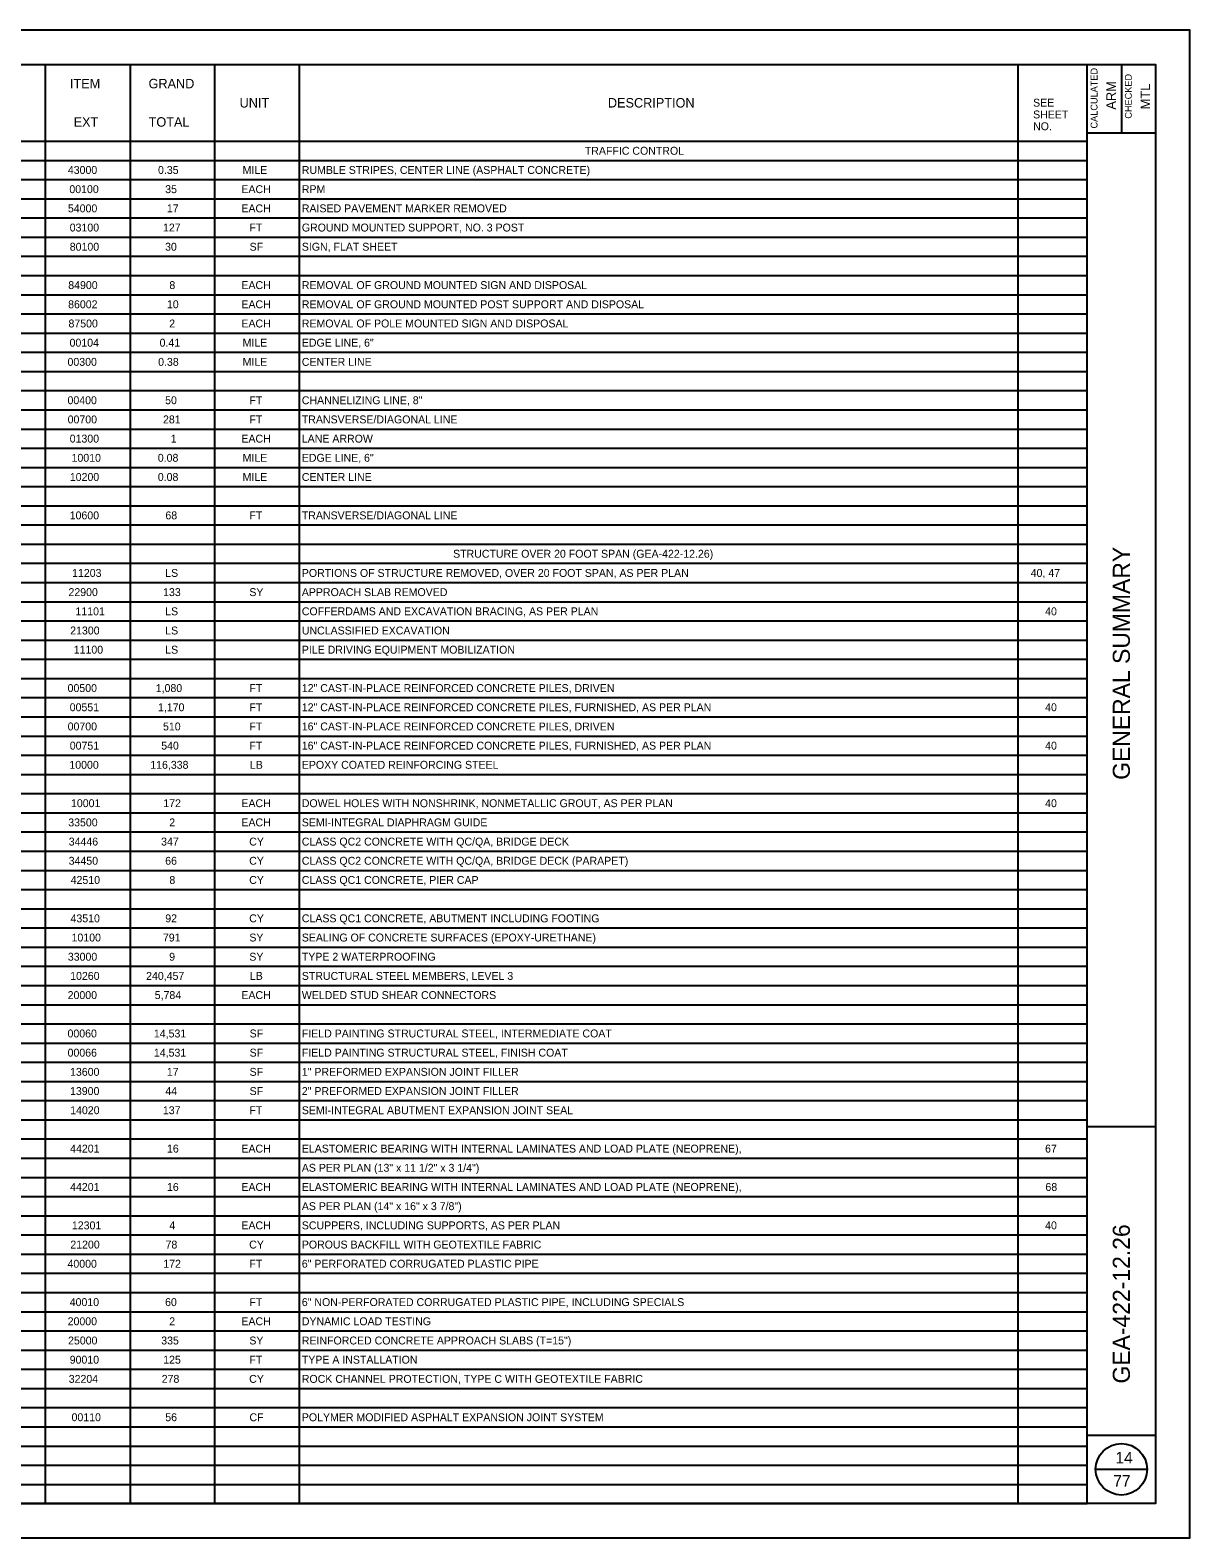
# Model space of a CAD drawing. Extents: x 0 to 34, y 0 to 22.
# Drawn here: x 17.07 to 34, y 0 to 22 of the extents above; entities that cross this region are included whole.
import ezdxf

# ---------------------------------------------------------------- set-up
doc = ezdxf.new("R2010")
doc.units = 0
for name, color, linetype in [('SH_Border', 7, 'Continuous'), ('SH_Cut_Line', 7, 'Continuous'), ('SH_Data', 7, 'Continuous'), ('SH_Text', 7, 'Continuous')]:
    doc.layers.add(name, color=color, linetype=linetype)

msp = doc.modelspace()

# ---------------------------------------------------------------- linework, layer by layer
at = {"layer": 'SH_Border'}
for p, q in [((32.5, 0.5), (32.5, 21.5)), ((33, 21.5), (33, 20.5)), ((32.5, 20.5), (33.5, 20.5)), ((32.5, 6), (33.5, 6)), ((32.5, 1.5), (33.5, 1.5))]:
    msp.add_line(p, q, dxfattribs=at)
msp.add_lwpolyline([(2, 21.5), (33.5, 21.5), (33.5, 0.5), (2, 0.5)], close=True, dxfattribs=at)
at = {"layer": 'SH_Cut_Line'}
msp.add_lwpolyline([(0, 0), (34, 0), (34, 22), (0, 22)], close=True, dxfattribs=at)
at = {"layer": 'SH_Data'}
msp.add_line((32.625, 1), (33.375, 1), dxfattribs=at)
msp.add_circle((33, 1), 0.375, dxfattribs=at)
at = {"layer": 'SH_Text'}
for p, q in [((2, 21.5), (32.5, 21.5)), ((17.299, 0.5), (17.299, 21.5)), ((18.535, 0.5), (18.535, 21.5)), ((19.77, 0.5), (19.77, 21.5)), ((21.005, 0.5), (21.005, 21.5)), ((31.495, 0.5), (31.495, 21.5)), ((32.5, 0.5), (32.5, 21.5)), ((14.055, 20.38), (32.5, 20.38)), ((19.77, 20.38), (32.5, 20.38)), ((2, 20.1), (32.5, 20.1)), ((2, 19.82), (32.5, 19.82)), ((2, 19.54), (32.5, 19.54)), ((2, 19.26), (32.5, 19.26)), ((2, 18.98), (32.5, 18.98)), ((2, 18.7), (32.5, 18.7)), ((2, 18.42), (32.5, 18.42)), ((2, 18.14), (32.5, 18.14)), ((2, 17.86), (32.5, 17.86)), ((2, 17.58), (32.5, 17.58)), ((2, 17.3), (32.5, 17.3)), ((2, 17.02), (32.5, 17.02)), ((2, 16.74), (32.5, 16.74)), ((2, 16.46), (32.5, 16.46)), ((2, 16.18), (32.5, 16.18)), ((2, 15.9), (32.5, 15.9)), ((2, 15.62), (32.5, 15.62)), ((2, 15.34), (32.5, 15.34)), ((2, 15.06), (32.5, 15.06)), ((2, 14.78), (32.5, 14.78)), ((2, 14.5), (32.5, 14.5)), ((2, 14.22), (32.5, 14.22)), ((2, 13.94), (32.5, 13.94)), ((2, 13.66), (32.5, 13.66)), ((2, 13.38), (32.5, 13.38)), ((2, 13.1), (32.5, 13.1)), ((2, 12.82), (32.5, 12.82)), ((2, 12.54), (32.5, 12.54)), ((2, 12.26), (32.5, 12.26)), ((2, 11.98), (32.5, 11.98)), ((2, 11.7), (32.5, 11.7)), ((2, 11.42), (32.5, 11.42)), ((2, 11.14), (32.5, 11.14)), ((2, 10.86), (32.5, 10.86)), ((2, 10.58), (32.5, 10.58)), ((2, 10.3), (32.5, 10.3)), ((2, 10.02), (32.5, 10.02)), ((2, 9.74), (32.5, 9.74)), ((2, 9.46), (32.5, 9.46)), ((2, 9.18), (32.5, 9.18)), ((2, 8.9), (32.5, 8.9)), ((2, 8.62), (32.5, 8.62)), ((2, 8.34), (32.5, 8.34)), ((2, 8.06), (32.5, 8.06)), ((2, 7.78), (32.5, 7.78)), ((2, 7.5), (32.5, 7.5)), ((2, 7.22), (32.5, 7.22)), ((2, 6.94), (32.5, 6.94)), ((2, 6.66), (32.5, 6.66)), ((2, 6.38), (32.5, 6.38)), ((2, 6.1), (32.5, 6.1)), ((2, 5.82), (32.5, 5.82)), ((2, 5.54), (32.5, 5.54)), ((2, 5.26), (32.5, 5.26)), ((2, 4.98), (32.5, 4.98)), ((2, 4.7), (32.5, 4.7)), ((2, 4.42), (32.5, 4.42)), ((2, 4.14), (32.5, 4.14)), ((2, 3.86), (32.5, 3.86)), ((2, 3.58), (32.5, 3.58)), ((2, 3.3), (32.5, 3.3)), ((2, 3.02), (32.5, 3.02)), ((2, 2.74), (32.5, 2.74)), ((2, 2.46), (32.5, 2.46)), ((2, 2.18), (32.5, 2.18)), ((2, 1.9), (32.5, 1.9)), ((2, 1.62), (32.5, 1.62)), ((2, 1.34), (32.5, 1.34)), ((2, 1.06), (32.5, 1.06)), ((2, 0.78), (32.5, 0.78)), ((2, 0.5), (32.5, 0.5))]:
    msp.add_line(p, q, dxfattribs=at)

# ---------------------------------------------------------------- texts
at = {"layer": 'SH_Data'}
for s, height, p in [('CALCULATED', 0.1, (32.652, 20.565)), ('CHECKED', 0.1, (33.152, 20.708)), ('ARM', 0.14, (32.92, 20.84)), ('MTL', 0.14, (33.42, 20.844)), ('GENERAL SUMMARY', 0.25, (33.125, 11.061)), ('GEA-422-12.26', 0.25, (33.125, 2.252))]:
    msp.add_text(s, height=height, rotation=90, dxfattribs=at).set_placement(p)
for s, p in [('14', (32.914, 1.085)), ('77', (32.882, 0.745))]:
    msp.add_text(s, height=0.17, dxfattribs=at).set_placement(p)
at = {"layer": 'SH_Text'}
for s, height, p in [('ITEM', 0.1384, (17.654, 21.151)), ('GRAND', 0.1384, (18.801, 21.151)), ('UNIT', 0.1384, (20.13, 20.871)), ('DESCRIPTION', 0.13841, (25.506, 20.871)), ('SEE', 0.1153, (31.712, 20.884)), ('EXT', 0.1384, (17.707, 20.591)), ('TOTAL', 0.1384, (18.802, 20.591)), ('SHEET', 0.1153, (31.712, 20.712)), ('NO.', 0.1153, (31.712, 20.54)), ('TRAFFIC CONTROL', 0.11534, (25.169, 20.182)), ('RUMBLE STRIPES, CENTER LINE (ASPHALT CONCRETE) ', 0.11534, (21.038, 19.902)), ('43000', 0.1153, (17.623, 19.902)), ('0.35', 0.1153, (18.939, 19.902)), ('MILE', 0.1153, (20.174, 19.902)), ('00100', 0.1153, (17.645, 19.622)), ('35', 0.1153, (19.044, 19.622)), ('EACH', 0.1153, (20.156, 19.622)), ('RPM ', 0.1153, (21.038, 19.622)), ('54000', 0.1153, (17.624, 19.342)), ('17', 0.1153, (19.068, 19.342)), ('EACH', 0.1153, (20.156, 19.342)), ('RAISED PAVEMENT MARKER REMOVED ', 0.11534, (21.038, 19.342)), ('03100', 0.1153, (17.65, 19.062)), ('127', 0.1153, (19.012, 19.062)), ('FT', 0.1153, (20.272, 19.062)), ('GROUND MOUNTED SUPPORT, NO. 3 POST ', 0.11534, (21.038, 19.062)), ('80100', 0.1153, (17.651, 18.782)), ('30', 0.1153, (19.042, 18.782)), ('SF', 0.1153, (20.276, 18.782)), ('SIGN, FLAT SHEET ', 0.11534, (21.038, 18.782)), ('84900', 0.1153, (17.629, 18.222)), ('8', 0.115, (19.105, 18.222)), ('EACH', 0.1153, (20.156, 18.222)), ('REMOVAL OF GROUND MOUNTED SIGN AND DISPOSAL ', 0.11534, (21.038, 18.222)), ('86002', 0.1153, (17.627, 17.942)), ('10', 0.1153, (19.069, 17.942)), ('EACH', 0.1153, (20.156, 17.942)), ('REMOVAL OF GROUND MOUNTED POST SUPPORT AND DISPOSAL ', 0.11534, (21.038, 17.942)), ('87500', 0.1153, (17.632, 17.662)), ('2', 0.115, (19.103, 17.662)), ('EACH', 0.1153, (20.156, 17.662)), ('REMOVAL OF POLE MOUNTED SIGN AND DISPOSAL ', 0.11534, (21.038, 17.662)), ('00104', 0.1153, (17.648, 17.382)), ('0.41', 0.1153, (18.962, 17.382)), ('MILE', 0.1153, (20.174, 17.382)), ('EDGE LINE, 6"', 0.11534, (21.038, 17.382)), ('00300', 0.1153, (17.618, 17.102)), ('0.38', 0.1153, (18.941, 17.102)), ('MILE', 0.1153, (20.174, 17.102)), ('CENTER LINE ', 0.11534, (21.038, 17.102)), ('00400', 0.1153, (17.618, 16.542)), ('50', 0.1153, (19.043, 16.542)), ('FT', 0.1153, (20.272, 16.542)), ('CHANNELIZING LINE, 8" ', 0.11534, (21.038, 16.542)), ('00700', 0.1153, (17.62, 16.262)), ('281', 0.1153, (19.012, 16.262)), ('FT', 0.1153, (20.272, 16.262)), ('TRANSVERSE/DIAGONAL LINE ', 0.11534, (21.038, 16.262)), ('01300', 0.1153, (17.65, 15.982)), ('1', 0.115, (19.125, 15.982)), ('EACH', 0.1153, (20.156, 15.982)), ('LANE ARROW ', 0.11534, (21.038, 15.982)), ('10010', 0.1153, (17.677, 15.702)), ('0.08', 0.1153, (18.936, 15.702)), ('MILE', 0.1153, (20.174, 15.702)), ('EDGE LINE, 6" ', 0.11534, (21.038, 15.702)), ('10200', 0.1153, (17.652, 15.422)), ('0.08', 0.1153, (18.936, 15.422)), ('MILE', 0.1153, (20.174, 15.422)), ('CENTER LINE ', 0.11534, (21.038, 15.422)), ('10600', 0.1153, (17.65, 14.862)), ('68', 0.1153, (19.047, 14.862)), ('FT', 0.1153, (20.272, 14.862)), ('TRANSVERSE/DIAGONAL LINE ', 0.11534, (21.038, 14.862)), ('STRUCTURE OVER 20 FOOT SPAN (GEA-422-12.26)', 0.11534, (23.246, 14.302)), ('11203', 0.1153, (17.685, 14.022)), ('LS', 0.1153, (19.044, 14.022)), ('PORTIONS OF STRUCTURE REMOVED, OVER 20 FOOT SPAN, AS PER PLAN', 0.11534, (21.038, 14.022)), ('40, 47', 0.1153, (31.677, 14.022)), ('22900', 0.1153, (17.632, 13.742)), ('133', 0.1153, (19.013, 13.742)), ('SY', 0.1153, (20.272, 13.742)), ('APPROACH SLAB REMOVED', 0.11534, (21.038, 13.742)), ('11101', 0.1153, (17.734, 13.462)), ('LS', 0.1153, (19.044, 13.462)), ('COFFERDAMS AND EXCAVATION BRACING, AS PER PLAN', 0.11534, (21.038, 13.462)), ('40', 0.1153, (31.888, 13.462)), ('21300', 0.1153, (17.657, 13.182)), ('LS', 0.1153, (19.044, 13.182)), ('UNCLASSIFIED EXCAVATION', 0.11534, (21.038, 13.182)), ('11100', 0.1153, (17.709, 12.902)), ('LS', 0.1153, (19.044, 12.902)), ('PILE DRIVING EQUIPMENT MOBILIZATION', 0.11534, (21.038, 12.902)), ('00500', 0.1153, (17.619, 12.342)), ('1,080', 0.1153, (18.906, 12.342)), ('FT', 0.1153, (20.272, 12.342)), ('12" CAST-IN-PLACE REINFORCED CONCRETE PILES, DRIVEN', 0.11534, (21.038, 12.342)), ('00551', 0.1153, (17.65, 12.062)), ('1,170', 0.1153, (18.939, 12.062)), ('FT', 0.1153, (20.272, 12.062)), ('12" CAST-IN-PLACE REINFORCED CONCRETE PILES, FURNISHED, AS PER PLAN', 0.11534, (21.038, 12.062)), ('40', 0.1153, (31.888, 12.062)), ('00700', 0.1153, (17.62, 11.782)), ('510', 0.1153, (19.012, 11.782)), ('FT', 0.1153, (20.272, 11.782)), ('16" CAST-IN-PLACE REINFORCED CONCRETE PILES, DRIVEN', 0.11534, (21.038, 11.782)), ('00751', 0.1153, (17.651, 11.502)), ('540', 0.1153, (18.986, 11.502)), ('FT', 0.1153, (20.272, 11.502)), ('16" CAST-IN-PLACE REINFORCED CONCRETE PILES, FURNISHED, AS PER PLAN', 0.11534, (21.038, 11.502)), ('40', 0.1153, (31.888, 11.502)), ('10000', 0.1153, (17.645, 11.222)), ('116,338', 0.1153, (18.826, 11.222)), ('LB', 0.1153, (20.28, 11.222)), ('EPOXY COATED REINFORCING STEEL', 0.11534, (21.038, 11.222)), ('10001', 0.1153, (17.669, 10.662)), ('172', 0.1153, (19.016, 10.662)), ('EACH', 0.1153, (20.156, 10.662)), ('DOWEL HOLES WITH NONSHRINK, NONMETALLIC GROUT, AS PER PLAN', 0.11534, (21.038, 10.662)), ('40', 0.1153, (31.888, 10.662)), ('33500', 0.1153, (17.629, 10.382)), ('2', 0.115, (19.103, 10.382)), ('EACH', 0.1153, (20.156, 10.382)), ('SEMI-INTEGRAL DIAPHRAGM GUIDE', 0.11534, (21.038, 10.382)), ('34446', 0.1153, (17.636, 10.102)), ('347', 0.1153, (18.984, 10.102)), ('CY', 0.1153, (20.27, 10.102)), ('CLASS QC2 CONCRETE WITH QC/QA, BRIDGE DECK', 0.11534, (21.038, 10.102)), ('34450', 0.1153, (17.635, 9.822)), ('66', 0.1153, (19.044, 9.822)), ('CY', 0.1153, (20.27, 9.822)), ('CLASS QC2 CONCRETE WITH QC/QA, BRIDGE DECK (PARAPET)', 0.11534, (21.038, 9.822)), ('42510', 0.1153, (17.664, 9.542)), ('8', 0.115, (19.105, 9.542)), ('CY', 0.1153, (20.27, 9.542)), ('CLASS QC1 CONCRETE, PIER CAP', 0.11534, (21.038, 9.542)), ('43510', 0.1153, (17.662, 8.982)), ('92', 0.1153, (19.045, 8.982)), ('CY', 0.1153, (20.27, 8.982)), ('CLASS QC1 CONCRETE, ABUTMENT INCLUDING FOOTING', 0.11534, (21.038, 8.982)), ('10100', 0.1153, (17.677, 8.702)), ('791', 0.1153, (19.011, 8.702)), ('SY', 0.1153, (20.272, 8.702)), ('SEALING OF CONCRETE SURFACES (EPOXY-URETHANE)', 0.11534, (21.038, 8.702)), ('33000', 0.1153, (17.623, 8.422)), ('9', 0.115, (19.102, 8.422)), ('SY', 0.1153, (20.272, 8.422)), ('TYPE 2 WATERPROOFING', 0.11534, (21.038, 8.422)), ('10260', 0.1153, (17.657, 8.142)), ('240,457', 0.1153, (18.765, 8.142)), ('LB', 0.1153, (20.28, 8.142)), ('STRUCTURAL STEEL MEMBERS, LEVEL 3', 0.11534, (21.038, 8.142)), ('20000', 0.1153, (17.62, 7.862)), ('5,784', 0.1153, (18.891, 7.862)), ('EACH', 0.1153, (20.156, 7.862)), ('WELDED STUD SHEAR CONNECTORS', 0.11534, (21.038, 7.862)), ('00060', 0.1153, (17.618, 7.302)), ('14,531', 0.1153, (18.879, 7.302)), ('SF', 0.1153, (20.276, 7.302)), ('FIELD PAINTING STRUCTURAL STEEL, INTERMEDIATE COAT', 0.11534, (21.038, 7.302)), ('00066', 0.1153, (17.619, 7.022)), ('14,531', 0.1153, (18.879, 7.022)), ('SF', 0.1153, (20.276, 7.022)), ('FIELD PAINTING STRUCTURAL STEEL, FINISH COAT', 0.11534, (21.038, 7.022)), ('13600', 0.1153, (17.655, 6.742)), ('17', 0.1153, (19.068, 6.742)), ('SF', 0.1153, (20.276, 6.742)), ('1" PREFORMED EXPANSION JOINT FILLER', 0.11534, (21.038, 6.742)), ('13900', 0.1153, (17.655, 6.462)), ('44', 0.1153, (19.046, 6.462)), ('SF', 0.1153, (20.276, 6.462)), ('2" PREFORMED EXPANSION JOINT FILLER', 0.11534, (21.038, 6.462)), ('14020', 0.1153, (17.657, 6.182)), ('137', 0.1153, (19.01, 6.182)), ('FT', 0.1153, (20.272, 6.182)), ('SEMI-INTEGRAL ABUTMENT EXPANSION JOINT SEAL', 0.11534, (21.038, 6.182)), ('44201', 0.1153, (17.656, 5.622)), ('16', 0.1153, (19.07, 5.622)), ('EACH', 0.1153, (20.156, 5.622)), ('ELASTOMERIC BEARING WITH INTERNAL LAMINATES AND LOAD PLATE (NEOPRENE),', 0.11534, (21.038, 5.622)), ('67', 0.1153, (31.887, 5.622)), ('AS PER PLAN (13" x 11 1/2" x 3 1/4")', 0.11534, (21.038, 5.342)), ('44201', 0.1153, (17.656, 5.062)), ('16', 0.1153, (19.07, 5.062)), ('EACH', 0.1153, (20.156, 5.062)), ('ELASTOMERIC BEARING WITH INTERNAL LAMINATES AND LOAD PLATE (NEOPRENE),', 0.11534, (21.038, 5.062)), ('68', 0.1153, (31.892, 5.062)), ('AS PER PLAN (14" x 16" x 3 7/8")', 0.11534, (21.038, 4.782)), ('12301', 0.1153, (17.682, 4.502)), ('4', 0.115, (19.104, 4.502)), ('EACH', 0.1153, (20.156, 4.502)), ('SCUPPERS, INCLUDING SUPPORTS, AS PER PLAN', 0.11534, (21.038, 4.502)), ('40', 0.1153, (31.888, 4.502)), ('21200', 0.1153, (17.659, 4.222)), ('78', 0.1153, (19.049, 4.222)), ('CY', 0.1153, (20.27, 4.222)), ('POROUS BACKFILL WITH GEOTEXTILE FABRIC', 0.11534, (21.038, 4.222)), ('40000', 0.1153, (17.618, 3.942)), ('172', 0.1153, (19.016, 3.942)), ('FT', 0.1153, (20.272, 3.942)), ('6" PERFORATED CORRUGATED PLASTIC PIPE', 0.11534, (21.038, 3.942)), ('40010', 0.1153, (17.65, 3.382)), ('60', 0.1153, (19.042, 3.382)), ('FT', 0.1153, (20.272, 3.382)), ('6" NON-PERFORATED CORRUGATED PLASTIC PIPE, INCLUDING SPECIALS', 0.11534, (21.038, 3.382)), ('20000', 0.1153, (17.62, 3.102)), ('2', 0.115, (19.103, 3.102)), ('EACH', 0.1153, (20.156, 3.102)), ('DYNAMIC LOAD TESTING', 0.11534, (21.038, 3.102)), ('25000', 0.1153, (17.626, 2.822)), ('335', 0.1153, (18.986, 2.822)), ('SY', 0.1153, (20.272, 2.822)), ('REINFORCED CONCRETE APPROACH SLABS (T=15")', 0.11534, (21.038, 2.822)), ('90010', 0.1153, (17.65, 2.542)), ('125', 0.1153, (19.015, 2.542)), ('FT', 0.1153, (20.272, 2.542)), ('TYPE A INSTALLATION', 0.11534, (21.038, 2.542)), ('32204', 0.1153, (17.636, 2.262)), ('278', 0.1153, (18.993, 2.262)), ('CY', 0.1153, (20.27, 2.262)), ('ROCK CHANNEL PROTECTION, TYPE C WITH GEOTEXTILE FABRIC', 0.11534, (21.038, 2.262)), ('00110', 0.1153, (17.677, 1.702)), ('56', 0.1153, (19.045, 1.702)), ('CF', 0.1153, (20.274, 1.702)), ('POLYMER MODIFIED ASPHALT EXPANSION JOINT SYSTEM', 0.11534, (21.038, 1.702))]:
    msp.add_text(s, height=height, dxfattribs=at).set_placement(p)

doc.saveas('drawing.dxf')
